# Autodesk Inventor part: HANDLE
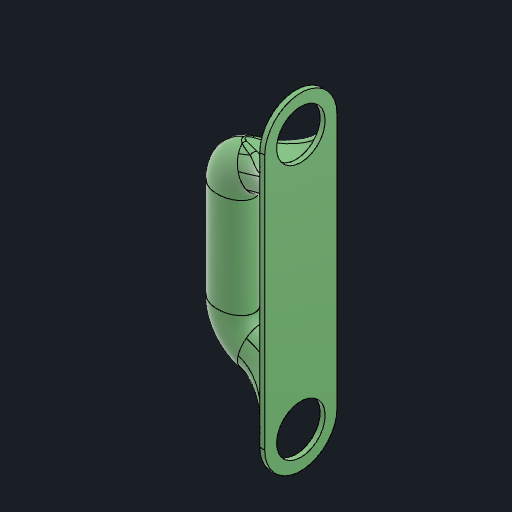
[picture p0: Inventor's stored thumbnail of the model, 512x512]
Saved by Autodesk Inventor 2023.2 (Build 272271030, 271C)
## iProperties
Created: 2023-01
Part Number: HANDLE
Material: Generic
Document SubType Name: Modeling
Designer: AR
Mass: 201.453 g
Surface Area: 467.997 cm^2
Volume: 201.453 cm^3
Density: 1 g/cm^3
Appearance: Smooth - Light Orange
Author: AR
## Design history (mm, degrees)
derived "_2 SPOOL CORD WRAP MP.ipt"
feature "PRUSA HANDLE::_2 SPOOL CORD WRAP MP.ipt" dims "d0" = 10
tag "TaggingFeature2"
node "PRUSA HANDLE"
